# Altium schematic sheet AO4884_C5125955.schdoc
size 127 x 101 mm
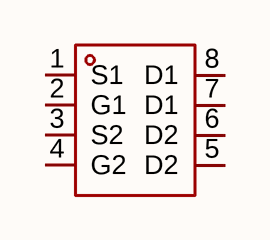
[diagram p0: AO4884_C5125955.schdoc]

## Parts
Q?  ao4884_c5125955  [SOP-8_L4.9-W3.9-P1.27-LS6.0-BL]  (value not drawn)

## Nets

Not connected (* = marked no-connect by the designer): Q? 1(S1) 2(G1) 3(S2) 4(G2) 5(D2) 6(D2) 7(D1) 8(D1)

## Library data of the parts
Q? = ao4884_c5125955: 数量:2个N沟道;漏源电压(Vdss):40V;连续漏极电流(Id):10A;导通电阻(RDS(on)):11mΩ@10V；12mΩ@4.5V;耗散功率(Pd):2W;阈值电压(Vgs(th)):1.5V@250uA;; Manufacturer: UMW(友台半导体); ManufacturerPart: AO4884; AddInBom: yes; ModelId: 75c24a7891ee4dd6bdac16a7163ff87e; ModelName: SOP-8_L4.9-W3.9-P1.27-LS6.0-BL-1; ModelTransform: 192.913,236.22,0,0,0,0,-0.393,2.749,0; Number: 2个N沟道; Drain to Source Voltage: 40V; Current - Continuous Drain(Id): 10A; Pd - Power Dissipation: 2W; Gate Charge(Qg): 27.2nC@10V; Input Capacitance(Ciss): 1.5nF; Reverse Transfer Capacitance (Crss@Vds): 135pF; Output Capacitance(Coss): 215pF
